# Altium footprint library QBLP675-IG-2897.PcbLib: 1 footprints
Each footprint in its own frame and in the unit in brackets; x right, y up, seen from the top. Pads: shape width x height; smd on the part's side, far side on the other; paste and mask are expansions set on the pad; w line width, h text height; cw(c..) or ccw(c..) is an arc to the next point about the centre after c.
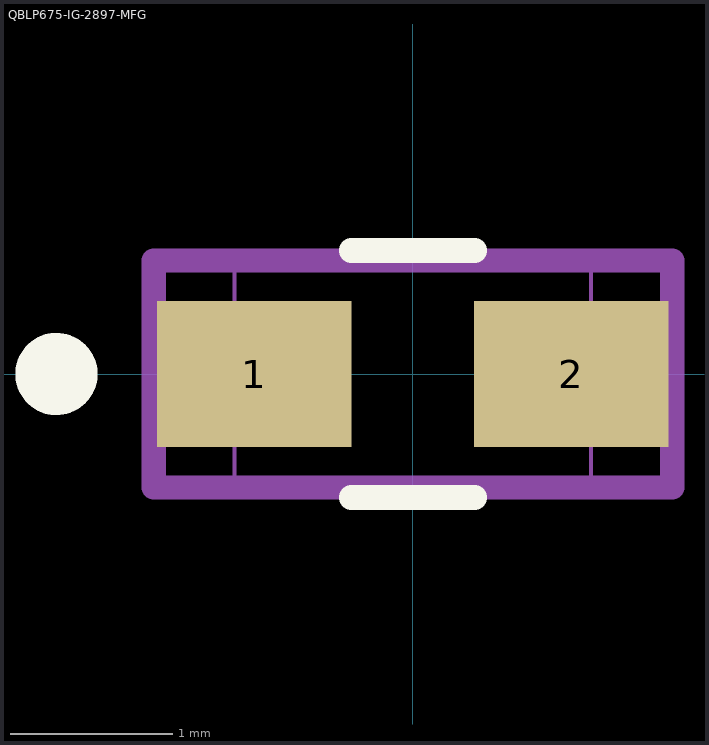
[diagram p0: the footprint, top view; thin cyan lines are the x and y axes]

## QBLP675-IG-2897-MFG [mm]
pads (2):
  rect 1.2x0.9 smd paste+0 mask+0: 1(-0.978,0) 2(0.978,0)
Top Overlay:
  circle w0.254: c-2.2,0 r0.127
  lines w0.152: -0.381,-0.762 0.381,-0.762 ; -0.381,0.762 0.381,0.762
Mechanical 5:
  lines w0.15: -1.6,-0.7 -1.6,0.7 1.6,0.7 1.6,-0.7 -1.6,-0.7
Mechanical 13:
  lines w0.025: -1.1,-0.7 -1.1,0.7 1.1,0.7 1.1,-0.7 -1.1,-0.7
Mechanical 15:
  lines w0.15: -1.6,-0.7 1.6,-0.7 1.6,0.7 -1.6,0.7 -1.6,-0.7
3D body "QBLP675.step": height 1.3, standoff 0, extent -1.1,-0.7 1.1,0.7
